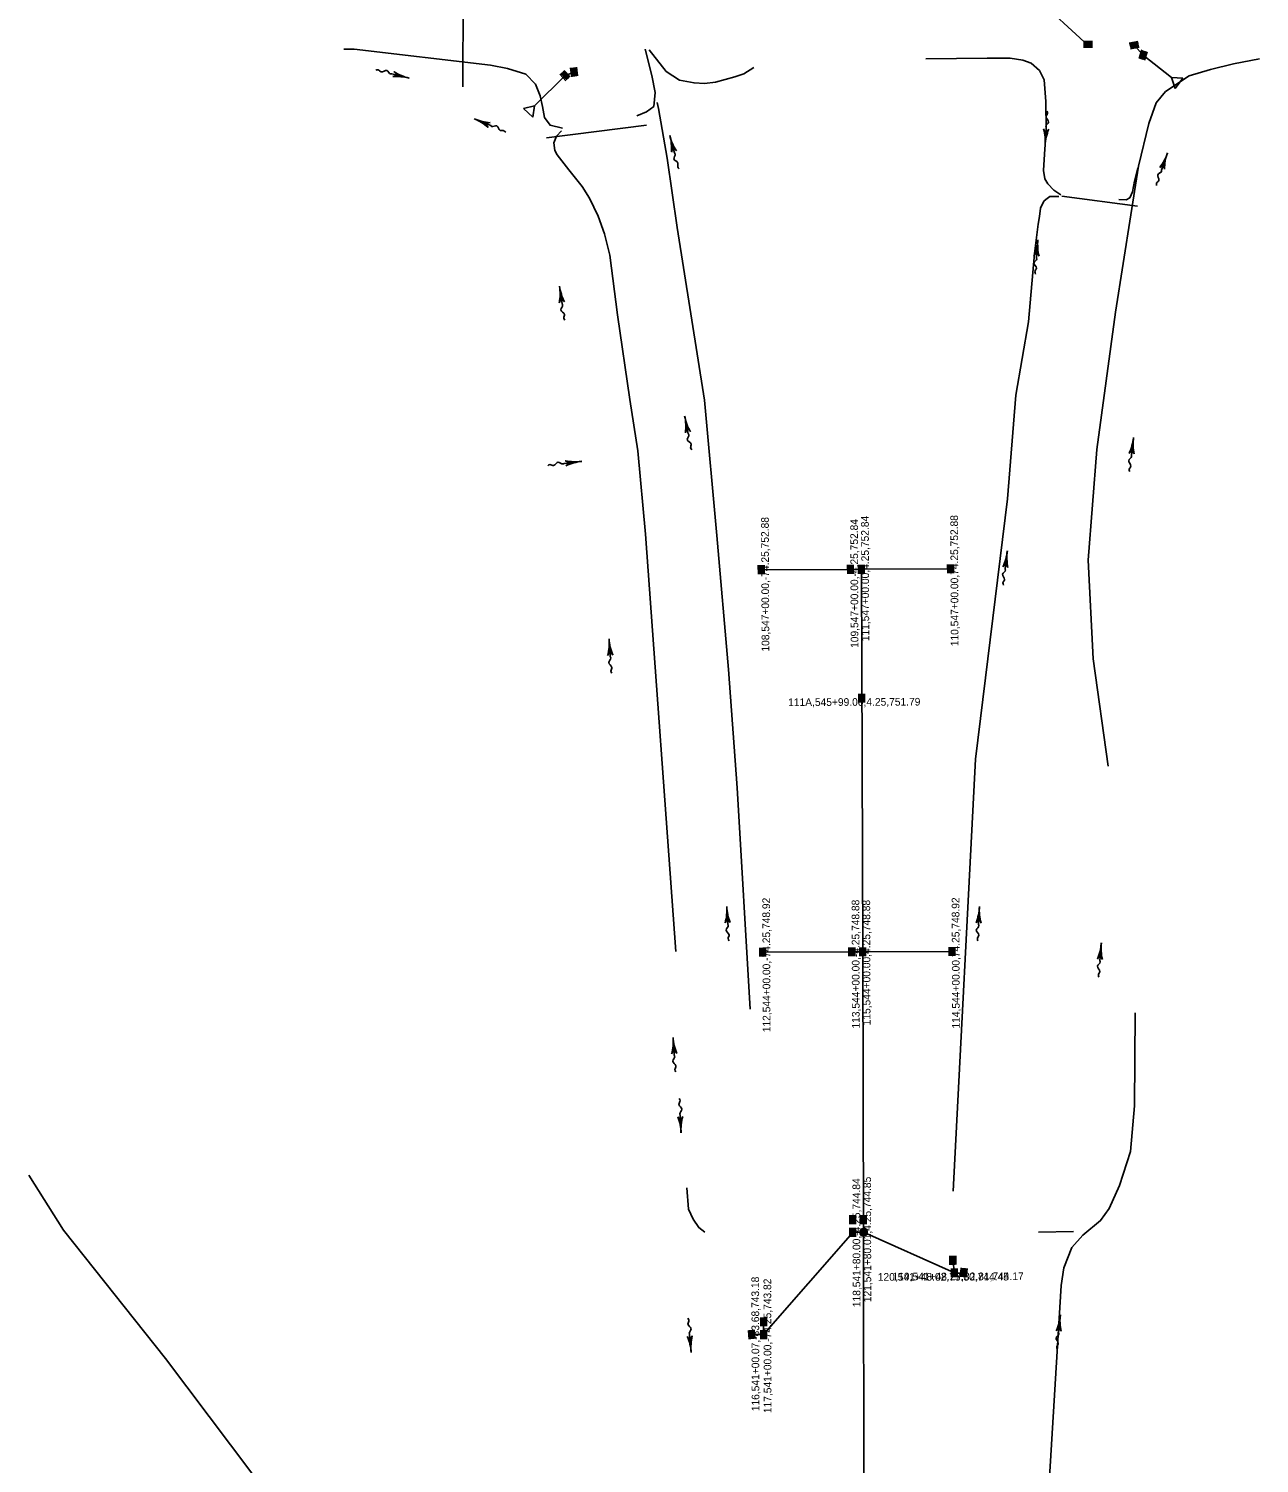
# Model space of a CAD drawing. Extents: x 593481 to 595859, y 150220 to 157407.
# Drawn here: x 593709 to 594675, y 153274 to 154399 of the extents above; entities that cross this region are included whole.
import ezdxf

# ---------------------------------------------------------------- set-up
doc = ezdxf.new("R2010")
doc.units = 0
for name, color, linetype in [('E_PROF_GridMin', 7, 'Continuous'), ('P_ALI_200_Equation', 7, 'Continuous'), ('P_ALI_20_Tic', 7, 'Continuous'), ('P_ALI_50_Equation', 7, 'Continuous'), ('P_DRN_Pipes', 7, 'Continuous'), ('P_DRN_SS_UG', 7, 'Continuous'), ('P_RDWY_C_and_G_H', 7, 'Continuous')]:
    doc.layers.add(name, color=color, linetype=linetype)

msp = doc.modelspace()

# ---------------------------------------------------------------- linework, layer by layer
at = {"layer": 'E_PROF_GridMin'}
for p, q in [((594540.5, 154386.1), (594491.5, 154431.2)), ((594576.6, 154386.3), (594583.6, 154378.5)), ((594583.6, 154378.5), (594605.8, 154360.9)), ((594137.3, 154365.2), (594130.2, 154362.4)), ((594130.2, 154362.4), (594106.2, 154338.6)), ((594284.1, 153974.9), (594354.1, 153975.2)), ((594354.1, 153975.2), (594362.6, 153975.3)), ((594432.6, 153975.5), (594362.6, 153975.3)), ((594362.6, 153975.3), (594363.7, 153675.3)), ((594285.2, 153675), (594355.2, 153675.2)), ((594355.2, 153675.2), (594363.7, 153675.3)), ((594433.7, 153675.5), (594363.7, 153675.3)), ((594363.7, 153675.3), (594364.3, 153455.3)), ((594285.9, 153375.1), (594355.8, 153455.2)), ((594355.8, 153455.2), (594364.3, 153455.3)), ((594435.6, 153423.4), (594364.3, 153455.3)), ((594364.3, 153455.3), (594364.8, 153184.2)), ((594529, 153456), (594501.6, 153455.4)), ((594435.6, 153423.4), (594434.3, 153433.4)), ((594285.9, 153375.1), (594285.9, 153385.1)), ((594276.5, 153375.1), (594285.9, 153375.1))]:
    msp.add_line(p, q, dxfattribs=at)
for points in [[(594128.3, 154321.1), (594118.4, 154323.4), (594114.1, 154329.6), (594112.5, 154338.2), (594110.8, 154346.4), (594107, 154355.8), (594099.4, 154363.4), (594085.1, 154367.9), (594071.8, 154370.5), (593964.7, 154383.1), (593956.8, 154383.2)], [(594193.1, 154383.1), (594198.4, 154362.4), (594201, 154349.1), (594199.9, 154338.2), (594194, 154334), (594186.5, 154330.9)], [(594196.2, 154382.7), (594209.6, 154365.5), (594220, 154358.9), (594231.4, 154356.6), (594239.5, 154356.1), (594248.2, 154357.3), (594263.3, 154361.5), (594270.5, 154363.9), (594278.3, 154368.7)], [(594519, 154268.8), (594513.7, 154272.6), (594508.9, 154277.5), (594506.6, 154281.5), (594505.5, 154288), (594506.3, 154300.9), (594507.7, 154319.7), (594507.3, 154342), (594506, 154359), (594502.3, 154366.3), (594495.9, 154372.1), (594489.3, 154374.5), (594479.3, 154376), (594461.3, 154376), (594413.1, 154375.6)], [(594674.8, 154375.5), (594654.5, 154371.6), (594636.6, 154367.3), (594619.8, 154362.1), (594601.1, 154349.9), (594593.8, 154341), (594588.1, 154324.9), (594580.1, 154291.4), (594561.9, 154177), (594547.4, 154069.1), (594540.5, 153982.3), (594544.4, 153905.1), (594556.2, 153820.9)], [(594202.5, 154341.4), (594203.4, 154336.5), (594210.2, 154297.7), (594218.2, 154243.4), (594239.5, 154107.8), (594249.3, 154001.8), (594258.4, 153896.6), (594265.3, 153803.8), (594275.5, 153630.4)], [(594127.3, 154319), (594123.6, 154314.8), (594121.4, 154309.7), (594122.3, 154303.6), (594124, 154300.2), (594133.1, 154288.5), (594143.6, 154275.3), (594149.5, 154266.4), (594156.2, 154252.1), (594161.2, 154238.3), (594165.2, 154221.7), (594171.3, 154174.7), (594181.1, 154108.4), (594187.2, 154068.1), (594193.4, 154002.9), (594217.2, 153675.5)], [(594579.4, 154290), (594576.9, 154279.6), (594575.4, 154271.3), (594573.1, 154266.5), (594570.2, 154264.9), (594564.5, 154265.3)], [(594517.6, 154267.7), (594510.4, 154267.7), (594507.4, 154265.3), (594505.7, 154263.8), (594503.2, 154258.4), (594502.3, 154251.9), (594501.3, 154245.8), (594498.5, 154222.8), (594493.6, 154169.3), (594483.9, 154111.8), (594477.3, 154030.5), (594452.1, 153826.4), (594434.7, 153487.6)], [(594577.5, 153627.4), (594576.8, 153554.4), (594573.6, 153518.6), (594565.2, 153492.1), (594557, 153474.1), (594550.3, 153464.5), (594536.3, 153453.1), (594527.8, 153443.5), (594521.5, 153427.4), (594519.3, 153413.7), (594507, 153211.5), (594503.1, 153118.7), (594500.3, 153076.8)], [(594231.3, 152595.8), (594238, 152608), (594241.5, 152629.1), (594238.7, 152654.6), (594233.1, 152686.7), (594216.9, 152735.1), (594189.3, 152811.5), (594166.9, 152857.5), (594145.5, 152897.2), (593987.3, 153130.1), (593816.8, 153356.3), (593736.8, 153457), (593709.5, 153500.1)], [(594239.9, 153455.5), (594235.1, 153459), (594230.6, 153465.7), (594227.1, 153473.5), (594225.7, 153490.3)]]:
    msp.add_lwpolyline(points, dxfattribs=at)
msp.add_arc((595235.5, -190446.6), 343870.9, 90.131684, 90.133649, dxfattribs=at)
at = {"layer": 'P_ALI_200_Equation'}
for radius in [2.98, 2.4, 1.8, 1.2, 0.6]:
    msp.add_circle((594364.3, 153455.3), radius, dxfattribs=at)
at = {"layer": 'P_ALI_20_Tic'}
for p, q in [((594008, 154360.4), (593994.3, 154363.9)), ((594058.9, 154328.6), (594071.9, 154323.2)), ((594506.8, 154307.6), (594507.7, 154321.7)), ((594212.3, 154315.3), (594216, 154301.7)), ((594602.7, 154301.7), (594598, 154288.3)), ((594501.1, 154233.7), (594499.9, 154219.7)), ((594125.8, 154197.3), (594127.9, 154183.3)), ((594224.1, 154095.3), (594226.8, 154081.5)), ((594576.1, 154078.6), (594574.4, 154064.6)), ((594143.4, 154059.9), (594129.4, 154058.3)), ((594477.1, 153989.6), (594475.4, 153975.6)), ((594164.7, 153920.7), (594165.7, 153906.6)), ((594257, 153710.9), (594257.8, 153696.8)), ((594455.2, 153710.7), (594454.5, 153696.6)), ((594550.8, 153682.3), (594549.7, 153668.2)), ((594214.9, 153608.1), (594215.9, 153594.1)), ((594221.2, 153533.2), (594220.5, 153547.3)), ((594518.7, 153390.7), (594517.3, 153376.6)), ((594229.1, 153361.1), (594227.9, 153375.2))]:
    msp.add_line(p, q, dxfattribs=at)
for points in [[(593995.1, 154361.6), (593998.7, 154362.7), (593996, 154365.5)], [(594069.9, 154321.8), (594067.7, 154324.9), (594071.5, 154325.5)], [(594505.6, 154320.5), (594507.4, 154317.2), (594509.6, 154320.3)], [(594217.5, 154303.5), (594214.8, 154306.1), (594213.7, 154302.4)], [(594600.4, 154288.9), (594599.5, 154292.6), (594596.6, 154290.3)], [(594502, 154220.8), (594500.3, 154224.2), (594498, 154221.1)], [(594129.7, 154184.9), (594127.2, 154187.8), (594125.7, 154184.3)], [(594228.5, 154083.2), (594225.9, 154085.9), (594224.6, 154082.4)], [(594130.9, 154056.4), (594133.9, 154058.8), (594130.5, 154060.4)], [(594576.5, 154065.7), (594575, 154069.1), (594572.6, 154066.1)], [(594477.6, 153976.7), (594476, 153980.1), (594473.6, 153977.2)], [(594167.6, 153908), (594165.4, 153911.1), (594163.6, 153907.7)], [(594259.7, 153698.2), (594257.5, 153701.3), (594255.7, 153698)], [(594456.5, 153697.9), (594454.7, 153701.2), (594452.6, 153698.1)], [(594551.8, 153669.3), (594550, 153672.7), (594547.8, 153669.7)], [(594217.8, 153595.5), (594215.6, 153598.6), (594213.8, 153595.2)], [(594218.6, 153545.9), (594220.7, 153542.8), (594222.6, 153546.1)], [(594226, 153373.7), (594228.3, 153370.6), (594230, 153374)], [(594519.4, 153377.7), (594517.7, 153381.1), (594515.4, 153378.1)]]:
    msp.add_lwpolyline(points, dxfattribs=at)
for centre, start, end in [((594018.2, 154401.1), 238.1531, 255.9155), ((593997.7, 154319.7), 75.9155, 93.6778), ((594042.8, 154289.8), 49.6888, 67.4512), ((594075, 154367.3), 247.4512, 265.2135), ((594464.9, 154310.2), 356.5125, 14.2748), ((594548.7, 154305.1), 158.7502, 176.5125), ((594252.8, 154326.3), 195.1541, 212.9164), ((594171.8, 154304.4), 357.3917, 15.1541), ((594563.1, 154315.5), 323.0209, 340.7832), ((594642.3, 154287.9), 160.7832, 178.5455), ((594459.2, 154237.1), 337.5935, 355.3558), ((594542.9, 154230.3), 175.3558, 193.1182), ((594084.3, 154191.1), 350.6256, 8.3879), ((594167.4, 154203.4), 188.3879, 206.1502), ((594265.2, 154103.5), 191.2545, 209.0168), ((594182.9, 154087.1), 353.4922, 11.2545), ((594534.5, 154083.7), 335.2209, 352.9833), ((594617.8, 154073.5), 172.9833, 190.7456), ((594138.6, 154101.6), 258.7469, 276.5092), ((594148.2, 154018.2), 96.5092, 114.2715), ((594435.5, 153994.8), 335.1954, 352.9578), ((594518.8, 153984.5), 172.9578, 190.7201), ((594122.9, 153917.6), 346.3551, 4.1174), ((594206.6, 153923.7), 184.1174, 201.8798), ((594215.1, 153708.4), 345.5959, 3.3582), ((594298.9, 153713.3), 183.3582, 201.1205), ((594413.3, 153712.9), 339.294, 357.0563), ((594497.1, 153708.6), 177.0563, 194.8186), ((594509, 153685.6), 337.6021, 355.3644), ((594592.6, 153678.9), 175.3644, 193.1267), ((594173.1, 153605.1), 346.3551, 4.1174), ((594256.8, 153611.2), 184.1174, 201.8798), ((594179.3, 153531.3), 2.5881, 20.3505), ((594263.1, 153535.1), 164.8258, 182.5881), ((594476.9, 153394.7), 336.6726, 354.435), ((594560.4, 153386.6), 174.435, 192.1973), ((594187.3, 153357.6), 4.6994, 22.4617), ((594270.9, 153364.5), 166.9371, 184.6994)]:
    msp.add_arc(centre, 42, start, end, dxfattribs=at)
for points in [[(593994.3, 154363.9), (593993.4, 154363.7), (593990.4, 154366.4), (593986, 154365.3), (593983.5, 154366.9), (593981.7, 154366.7)], [(594507.7, 154321.7), (594507.4, 154322.5), (594509.5, 154326), (594507.5, 154330.1), (594508.7, 154332.8), (594508.1, 154334.6)], [(594071.9, 154323.2), (594072.5, 154322.6), (594076.6, 154322.9), (594079.4, 154319.4), (594082.3, 154319.2), (594083.7, 154317.9)], [(594216, 154301.7), (594216.5, 154301), (594215.6, 154297), (594218.7, 154293.8), (594218.6, 154290.8), (594219.6, 154289.3)], [(594598, 154288.3), (594598.1, 154287.5), (594595.1, 154284.7), (594595.9, 154280.3), (594594.1, 154277.9), (594594.1, 154276.1)], [(594499.9, 154219.7), (594500.2, 154218.8), (594498, 154215.4), (594499.9, 154211.3), (594498.7, 154208.6), (594499.2, 154206.8)], [(594127.9, 154183.3), (594128.3, 154182.6), (594127, 154178.7), (594129.7, 154175.1), (594129.2, 154172.2), (594130.1, 154170.6)], [(594226.8, 154081.5), (594227.3, 154080.8), (594226.1, 154076.9), (594229.1, 154073.4), (594228.7, 154070.5), (594229.6, 154068.9)], [(594574.4, 154064.6), (594574.6, 154063.8), (594572.3, 154060.4), (594574, 154056.2), (594572.7, 154053.6), (594573.1, 154051.8)], [(594129.4, 154058.3), (594128.6, 154057.9), (594124.8, 154059.3), (594121.2, 154056.7), (594118.3, 154057.3), (594116.6, 154056.5)], [(594475.4, 153975.6), (594475.6, 153974.8), (594473.3, 153971.4), (594475, 153967.3), (594473.7, 153964.6), (594474.1, 153962.8)], [(594165.7, 153906.6), (594166.1, 153905.8), (594164.5, 153902.1), (594166.9, 153898.3), (594166.2, 153895.4), (594167, 153893.8)], [(594257.8, 153696.8), (594258.2, 153696), (594256.5, 153692.3), (594258.9, 153688.5), (594258.1, 153685.6), (594258.9, 153683.9)], [(594454.5, 153696.6), (594454.8, 153695.8), (594452.7, 153692.3), (594454.7, 153688.3), (594453.6, 153685.5), (594454.1, 153683.8)], [(594549.7, 153668.2), (594549.9, 153667.4), (594547.8, 153663.9), (594549.6, 153659.8), (594548.5, 153657.1), (594548.9, 153655.3)], [(594215.9, 153594.1), (594216.3, 153593.3), (594214.7, 153589.6), (594217.1, 153585.8), (594216.4, 153582.9), (594217.2, 153581.2)], [(594220.5, 153547.3), (594220.2, 153548.1), (594221.9, 153551.8), (594219.5, 153555.6), (594220.4, 153558.5), (594219.6, 153560.2)], [(594227.9, 153375.2), (594227.6, 153375.9), (594229.1, 153379.7), (594226.6, 153383.4), (594227.3, 153386.3), (594226.6, 153388)], [(594517.3, 153376.6), (594517.5, 153375.8), (594515.3, 153372.4), (594517.1, 153368.3), (594515.9, 153365.5), (594516.3, 153363.8)]]:
    msp.add_spline(points, degree=3, dxfattribs=at)
at = {"layer": 'P_DRN_Pipes'}
for p, q in [((594050.1, 154353.5), (594050.6, 154501.4)), ((594115.7, 154313.7), (594194.2, 154323.4)), ((594519.8, 154267.9), (594579.3, 154260))]:
    msp.add_line(p, q, dxfattribs=at)
at = {"layer": 'P_DRN_SS_UG'}
for p, q in [((594543.8, 154389.2), (594536.9, 154389.1)), ((594543.8, 154388.3), (594536.9, 154388.2)), ((594543.8, 154387.4), (594536.9, 154387.3)), ((594543.8, 154386.5), (594536.9, 154386.4)), ((594579.5, 154389.2), (594572.8, 154387.7)), ((594579.7, 154388.3), (594573, 154386.8)), ((594579.9, 154387.5), (594573.2, 154386)), ((594580.1, 154386.6), (594573.4, 154385.1)), ((594543.8, 154385.6), (594536.9, 154385.5)), ((594543.8, 154384.7), (594536.9, 154384.6)), ((594580.3, 154385.7), (594573.6, 154384.2)), ((594580.5, 154384.8), (594573.8, 154383.3)), ((594582.5, 154382.5), (594580.4, 154375.9)), ((594583.4, 154382.2), (594581.3, 154375.6)), ((594584.2, 154381.9), (594582.1, 154375.4)), ((594585.1, 154381.6), (594583, 154375.1)), ((594585.9, 154381.4), (594583.9, 154374.8)), ((594586.8, 154381.1), (594584.7, 154374.5)), ((594131.6, 154359), (594126.9, 154364)), ((594132.2, 154359.6), (594127.5, 154364.6)), ((594132.9, 154360.2), (594128.2, 154365.2)), ((594133.5, 154360.8), (594128.8, 154365.8)), ((594134.2, 154361.4), (594129.5, 154366.4)), ((594135.5, 154361.5), (594134.6, 154368.4)), ((594136.4, 154361.6), (594135.5, 154368.5)), ((594137.3, 154361.7), (594136.4, 154368.6)), ((594138.1, 154361.9), (594137.3, 154368.7)), ((594139, 154362), (594138.2, 154368.8)), ((594139.9, 154362.1), (594139.1, 154368.9)), ((594130.9, 154358.4), (594126.2, 154363.4)), ((594281.9, 153971.5), (594281.8, 153978.4)), ((594282.8, 153971.5), (594282.7, 153978.4)), ((594283.7, 153971.5), (594283.6, 153978.4)), ((594284.6, 153971.5), (594284.5, 153978.4)), ((594285.5, 153971.5), (594285.4, 153978.4)), ((594286.4, 153971.5), (594286.3, 153978.4)), ((594351.9, 153971.8), (594351.8, 153978.7)), ((594352.8, 153971.8), (594352.7, 153978.7)), ((594353.7, 153971.8), (594353.6, 153978.7)), ((594354.6, 153971.8), (594354.5, 153978.7)), ((594355.5, 153971.8), (594355.4, 153978.7)), ((594356.4, 153971.8), (594356.3, 153978.7)), ((594360.4, 153971.8), (594360.3, 153978.7)), ((594361.3, 153971.8), (594361.2, 153978.7)), ((594362.2, 153971.8), (594362.1, 153978.7)), ((594363.1, 153971.8), (594363, 153978.7)), ((594364, 153971.8), (594363.9, 153978.7)), ((594364.9, 153971.8), (594364.8, 153978.7)), ((594430.4, 153972.1), (594430.3, 153979)), ((594431.3, 153972.1), (594431.2, 153979)), ((594432.2, 153972.1), (594432.1, 153979)), ((594433.1, 153972.1), (594433, 153979)), ((594434, 153972.1), (594433.9, 153979)), ((594434.9, 153972.1), (594434.8, 153979)), ((594360.7, 153870.8), (594360.7, 153877.7)), ((594361.6, 153870.8), (594361.6, 153877.7)), ((594362.5, 153870.8), (594362.5, 153877.7)), ((594363.4, 153870.8), (594363.4, 153877.7)), ((594364.3, 153870.8), (594364.3, 153877.7)), ((594365.2, 153870.8), (594365.2, 153877.7)), ((594282.9, 153671.6), (594282.9, 153678.4)), ((594283.8, 153671.6), (594283.8, 153678.4)), ((594284.7, 153671.6), (594284.7, 153678.4)), ((594285.6, 153671.6), (594285.6, 153678.5)), ((594286.5, 153671.6), (594286.5, 153678.5)), ((594287.4, 153671.6), (594287.4, 153678.5)), ((594352.9, 153671.8), (594352.9, 153678.7)), ((594353.8, 153671.8), (594353.8, 153678.7)), ((594354.7, 153671.8), (594354.7, 153678.7)), ((594355.6, 153671.8), (594355.6, 153678.7)), ((594356.5, 153671.8), (594356.5, 153678.7)), ((594357.4, 153671.8), (594357.4, 153678.7)), ((594361.4, 153671.8), (594361.4, 153678.7)), ((594362.3, 153671.8), (594362.3, 153678.7)), ((594363.2, 153671.8), (594363.2, 153678.7)), ((594364.1, 153671.8), (594364.1, 153678.7)), ((594365, 153671.8), (594365, 153678.7)), ((594365.9, 153671.8), (594365.9, 153678.7)), ((594431.4, 153672), (594431.4, 153678.9)), ((594432.3, 153672), (594432.3, 153678.9)), ((594433.2, 153672), (594433.2, 153678.9)), ((594434.1, 153672), (594434.1, 153678.9)), ((594435, 153672), (594435, 153678.9)), ((594435.9, 153672), (594435.9, 153678.9)), ((594353.5, 153461.8), (594353.5, 153468.7)), ((594354.4, 153461.8), (594354.4, 153468.7)), ((594355.3, 153461.8), (594355.3, 153468.7)), ((594356.2, 153461.8), (594356.2, 153468.7)), ((594357.1, 153461.8), (594357.1, 153468.7)), ((594358, 153461.8), (594358, 153468.7)), ((594362, 153461.8), (594362, 153468.7)), ((594362.9, 153461.8), (594362.9, 153468.7)), ((594363.8, 153461.8), (594363.8, 153468.7)), ((594364.7, 153461.8), (594364.7, 153468.7)), ((594365.6, 153461.8), (594365.6, 153468.7)), ((594366.5, 153461.8), (594366.5, 153468.7)), ((594353.5, 153451.8), (594353.5, 153458.7)), ((594354.4, 153451.8), (594354.4, 153458.7)), ((594355.3, 153451.8), (594355.3, 153458.7)), ((594356.2, 153451.8), (594356.2, 153458.7)), ((594357.1, 153451.8), (594357.1, 153458.7)), ((594358, 153451.8), (594358, 153458.7)), ((594432.1, 153429.9), (594432.1, 153436.8)), ((594433, 153429.9), (594433, 153436.8)), ((594433.9, 153429.9), (594433.9, 153436.8)), ((594434.8, 153429.9), (594434.8, 153436.8)), ((594435.7, 153429.9), (594435.7, 153436.8)), ((594436.6, 153430), (594436.6, 153436.8)), ((594433.3, 153420), (594433.3, 153426.9)), ((594434.2, 153420), (594434.2, 153426.9)), ((594435.1, 153420), (594435.1, 153426.9)), ((594436, 153420), (594436, 153426.9)), ((594436.9, 153420), (594436.9, 153426.9)), ((594437.8, 153420), (594437.8, 153426.9)), ((594440.3, 153420.5), (594441, 153427.4)), ((594441.2, 153420.4), (594441.9, 153427.3)), ((594442.1, 153420.3), (594442.8, 153427.2)), ((594443, 153420.2), (594443.7, 153427.1)), ((594443.9, 153420.1), (594444.6, 153427)), ((594444.8, 153420), (594445.5, 153426.9)), ((594283.7, 153381.7), (594283.7, 153388.5)), ((594284.6, 153381.7), (594284.6, 153388.5)), ((594285.5, 153381.7), (594285.5, 153388.5)), ((594286.4, 153381.7), (594286.4, 153388.5)), ((594287.3, 153381.7), (594287.3, 153388.5)), ((594288.2, 153381.7), (594288.2, 153388.5)), ((594274.5, 153371.5), (594274, 153378.4)), ((594275.4, 153371.6), (594274.9, 153378.5)), ((594276.3, 153371.7), (594275.8, 153378.5)), ((594277.2, 153371.7), (594276.7, 153378.6)), ((594278.1, 153371.8), (594277.6, 153378.6)), ((594279, 153371.9), (594278.5, 153378.7)), ((594283.7, 153371.6), (594283.7, 153378.5)), ((594284.6, 153371.6), (594284.6, 153378.5)), ((594285.5, 153371.6), (594285.5, 153378.5)), ((594286.4, 153371.6), (594286.4, 153378.5)), ((594287.3, 153371.6), (594287.3, 153378.5)), ((594288.2, 153371.6), (594288.2, 153378.5))]:
    msp.add_line(p, q, dxfattribs=at)
for points in [[(594541.3, 154387.9), (594539.3, 154387.9), (594539.3, 154385.9), (594541.3, 154385.9)], [(594577.4, 154387.5), (594575.4, 154387), (594575.9, 154385.1), (594577.8, 154385.5)], [(594583, 154379.8), (594582.4, 154377.9), (594584.3, 154377.2), (594584.9, 154379.2)], [(594131.6, 154362.4), (594130.2, 154363.8), (594128.8, 154362.4), (594130.1, 154361)], [(594138.4, 154364.3), (594138.2, 154366.3), (594136.2, 154366.1), (594136.4, 154364.1)], [(594285.1, 153973.9), (594285.1, 153975.9), (594283.1, 153975.9), (594283.1, 153973.9)], [(594355.1, 153974.2), (594355.1, 153976.2), (594353.1, 153976.2), (594353.1, 153974.2)], [(594363.6, 153974.3), (594363.6, 153976.3), (594361.6, 153976.3), (594361.6, 153974.3)], [(594433.6, 153974.5), (594433.6, 153976.5), (594431.6, 153976.5), (594431.6, 153974.5)], [(594364, 153873.3), (594364, 153875.3), (594362, 153875.3), (594362, 153873.3)], [(594286.2, 153674), (594286.1, 153676), (594284.1, 153676), (594284.2, 153674)], [(594356.2, 153674.2), (594356.1, 153676.2), (594354.1, 153676.2), (594354.2, 153674.2)], [(594364.7, 153674.3), (594364.6, 153676.3), (594362.6, 153676.3), (594362.7, 153674.3)], [(594434.7, 153674.5), (594434.6, 153676.5), (594432.6, 153676.5), (594432.7, 153674.5)], [(594356.7, 153464.2), (594356.7, 153466.2), (594354.7, 153466.2), (594354.7, 153464.2)], [(594365.3, 153464.3), (594365.3, 153466.3), (594363.3, 153466.3), (594363.3, 153464.3)], [(594356.8, 153454.2), (594356.8, 153456.2), (594354.8, 153456.2), (594354.8, 153454.2)], [(594435.3, 153432.4), (594435.3, 153434.4), (594433.3, 153434.4), (594433.3, 153432.4)], [(594436.6, 153422.4), (594436.6, 153424.4), (594434.6, 153424.4), (594434.6, 153422.4)], [(594443.8, 153422.6), (594444, 153424.6), (594442, 153424.8), (594441.8, 153422.8)], [(594286.9, 153384.1), (594286.9, 153386.1), (594284.9, 153386.1), (594284.9, 153384.1)], [(594277.6, 153374.2), (594277.4, 153376.2), (594275.4, 153376.1), (594275.6, 153374.1)], [(594286.9, 153374.1), (594286.9, 153376.1), (594284.9, 153376.1), (594284.9, 153374.1)]]:
    msp.add_lwpolyline(points, close=True, dxfattribs=at)
at = {"layer": 'P_RDWY_C_and_G_H'}
for p, q in [((594614.8, 154360.3), (594605.8, 154360.9)), ((594605.8, 154360.9), (594608.7, 154352.4)), ((594614.8, 154360.3), (594608.7, 154352.4)), ((594106.2, 154338.6), (594097.5, 154336.5)), ((594104.8, 154329.7), (594097.5, 154336.5)), ((594104.8, 154329.7), (594106.2, 154338.6))]:
    msp.add_line(p, q, dxfattribs=at)

# ---------------------------------------------------------------- texts
at = {"layer": 'P_ALI_50_Equation'}
for s, rotation, p in [('108,547+00.00,-74.25,752.88', 90.2262, (594290.4, 153910.7)), ('111,547+00.00,4.25,752.84', 90.2262, (594368.8, 153918.8)), ('110,547+00.00,74.25,752.88', 90.2262, (594438.8, 153914.9)), ('109,547+00.00,-4.25,752.84', 90.2262, (594360.3, 153913.6)), ('111A,545+99.00,4.25,751.79', 0.2093, (594305.2, 153868)), ('112,544+00.00,-74.25,748.92', 90.1762, (594291.3, 153612.2)), ('113,544+00.00,-4.25,748.88', 90.1762, (594361.3, 153615.1)), ('115,544+00.00,4.25,748.88', 90.1762, (594369.8, 153617.6)), ('114,544+00.00,74.25,748.92', 90.1762, (594439.8, 153615.1)), ('118,541+80.00,-4.25,744.84', 90.1395, (594361.9, 153396.6)), ('121,541+80.01,4.25,744.85', 90.1395, (594370.4, 153400.5)), ('116,541+00.07,-83.68,743.18', 90.1262, (594282.6, 153315)), ('120,541+48.02,75.50,744.45', 0.1342, (594375.5, 153417.3)), ('119,541+48.27,82.81,744.17', 0.1342, (594387.1, 153417.6)), ('117,541+00.00,-74.25,743.82', 90.1262, (594292.1, 153313.5))]:
    msp.add_text(s, height=6, rotation=rotation, dxfattribs=at).set_placement(p)

doc.saveas('drawing.dxf')
